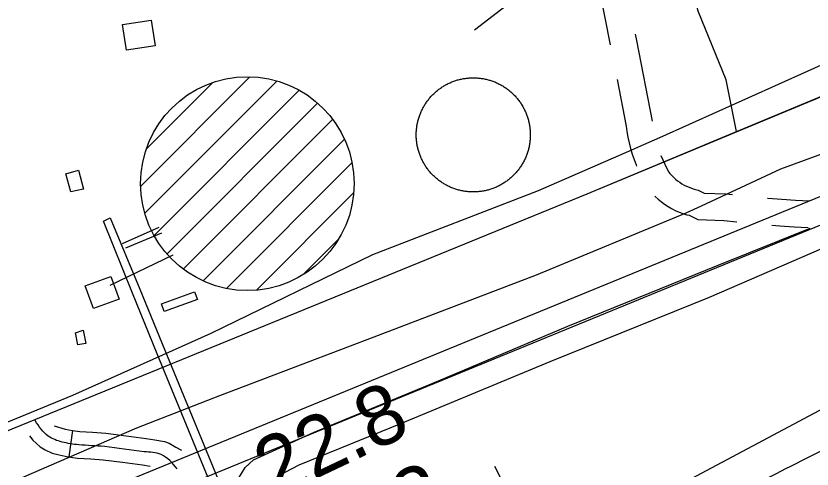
# Model space of a CAD drawing. Extents: x 3477039 to 3515015, y 546746 to 572297.
# Drawn here: x 3490723 to 3491621, y 565180 to 565690 of the extents above; entities that cross this region are included whole.
import ezdxf

# ---------------------------------------------------------------- set-up
doc = ezdxf.new("R2010")
doc.units = 0
for name, color, linetype in [('V-BLDG-OTLN', 7, 'Continuous'), ('V-DOMW-TANK', 7, 'Continuous'), ('V-FLOD-BASE', 7, 'Continuous'), ('V-LEVE-TOET', 7, 'Continuous'), ('V-RIVR-RANG', 7, 'Continuous'), ('V-ROAD-CNTR', 7, 'Continuous'), ('V-SITE-OTLN', 7, 'Continuous'), ('V-SITE-STRC', 7, 'Continuous'), ('V-SURV-LINE', 7, 'Continuous'), ('V-TOPO-MINR', 7, 'Continuous'), ('V-TOPO-SHOR', 7, 'Continuous'), ('V-UTIL-LINE', 7, 'Continuous')]:
    doc.layers.add(name, color=color, linetype=linetype)

msp = doc.modelspace()

# ---------------------------------------------------------------- linework, layer by layer
at = {"layer": 'V-BLDG-OTLN'}
for points in [[(3490875.75, 565685.23), (3490880.24, 565656.41), (3490847.93, 565651.37), (3490843.44, 565680.2)], [(3490799.44, 565495.05), (3490785.11, 565491.98), (3490779.51, 565512.16), (3490793.73, 565516.22)], [(3490839.59, 565370.95), (3490810.76, 565360.6), (3490801.59, 565386.16), (3490830.26, 565396.45)], [(3490928.18, 565370.91), (3490890.48, 565357.09), (3490887.33, 565365.82), (3490924.56, 565379.4)], [(3490799.26, 565336.03), (3490802.09, 565321.33), (3490793.15, 565319.61), (3490790.56, 565333.07)]]:
    msp.add_lwpolyline(points, close=True, dxfattribs=at)
at = {"layer": 'V-DOMW-TANK'}
for p, q in [((3490864.09, 565498.47), (3490986.95, 565621.33)), ((3490868.84, 565467.87), (3491017.61, 565616.64)), ((3490870.72, 565540.46), (3490944.98, 565614.72)), ((3490879.18, 565442.85), (3491042.7, 565606.37)), ((3490893.69, 565422.01), (3491063.33, 565591.65)), ((3490912.15, 565405.11), (3491080.35, 565573.32)), ((3490934.25, 565391.86), (3491093.67, 565551.28)), ((3490960.86, 565383.11), (3491102.18, 565524.44)), ((3490994.5, 565381.4), (3491104.15, 565491.05)), ((3491047.3, 565398.84), (3491086.35, 565437.9))]:
    msp.add_line(p, q, dxfattribs=at)
msp.add_circle((3490984.24, 565501.19), 120.38, dxfattribs=at)
at = {"layer": 'V-FLOD-BASE'}
msp.add_lwpolyline([(3490960.96, 565147.74), (3490981.75, 565181.62), (3490991.2, 565190.35), (3491059.5, 565221.52), (3491199.58, 565279.15), (3491345.56, 565340.84), (3491515.06, 565409.4), (3491618.64, 565450.87)], dxfattribs=at)
at = {"layer": 'V-LEVE-TOET'}
for points in [[(3491733.96, 565572.05), (3491585.1, 565517.43), (3491495.63, 565475.73), (3491478.53, 565467.76), (3491309.61, 565398.03), (3491134.84, 565331.27), (3490953.02, 565262.22), (3490859.45, 565225.95), (3490718.17, 565164.81), (3490576.91, 565106.02), (3490410.39, 565043.89), (3490383.11, 565035.49)], [(3491642.56, 565432.5), (3491504.81, 565373.1), (3491325.31, 565300.51), (3491156.97, 565230.77), (3491042.21, 565184.1), (3491018.64, 565171.95), (3491002.1, 565156.23), (3490973.57, 565107.75), (3490958.15, 565085.57), (3490949.9, 565081.52), (3490943.46, 565082.74), (3490907.83, 565105.31), (3490886.76, 565112.5), (3490869.76, 565113.8), (3490855.66, 565110.97), (3490841.54, 565106.39), (3490717.33, 565052.75), (3490582.56, 564998.6), (3490425.99, 564932.88), (3490344.85, 564899.28)]]:
    msp.add_lwpolyline(points, dxfattribs=at)
at = {"layer": 'V-ROAD-CNTR'}
msp.add_line((3490787.15, 565223.25), (3490783.09, 565193.52), dxfattribs=at)
for points in [[(3490529.31, 565147.85), (3491367.11, 565489.84), (3492727.74, 566054.53)], [(3491240.09, 565674.18), (3491275.99, 565701.54), (3491299.08, 565743.73), (3491305.03, 565770.31), (3491313.84, 565838.71), (3491328, 565872.96), (3491351.9, 565907.38), (3491386.23, 565937.6), (3491438.88, 565949.58), (3491522.88, 565981.17), (3491552.05, 565994.84), (3491588.38, 566018.94)], [(3491535.49, 565559.72), (3491523.85, 565617.9), (3491492.29, 565695.32), (3491472.88, 565768.14), (3491468.26, 565808.18), (3491479.57, 565829.14), (3491520.44, 565842.81), (3491575.69, 565851), (3491650, 565861.08), (3491647.65, 565868.29)], [(3491373.7, 565755.66), (3491375.41, 565747.18), (3491393.25, 565657.59)], [(3491421.44, 565669.62), (3491422.93, 565662.15), (3491440.72, 565571.5)], [(3491524.12, 565555), (3491737.96, 565643.75)], [(3491400.96, 565618.34), (3491411.27, 565565.8), (3491412.1, 565559.97), (3491413.26, 565553.53), (3491414.64, 565547.13), (3491416.25, 565540.79), (3491418.09, 565534.51), (3491420.15, 565528.3), (3491422.42, 565522.17), (3491422.92, 565520.96)], [(3490529.31, 565147.85), (3491367.11, 565489.84), (3491524.12, 565555)], [(3491450.48, 565532.82), (3491452.45, 565528.04), (3491454.71, 565523.06), (3491457.16, 565518.16), (3491459.27, 565514.27), (3491460.55, 565512.66), (3491462.54, 565510.43), (3491464.64, 565508.31), (3491466.85, 565506.31), (3491469.17, 565504.42), (3491471.59, 565502.67), (3491474.1, 565501.04), (3491476.68, 565499.56), (3491479.35, 565498.22), (3491482.08, 565497.03), (3491484.87, 565495.98), (3491487.71, 565495.09), (3491492.39, 565493.89), (3491499.29, 565490.6), (3491523.58, 565489.65), (3491531.04, 565488.78)], [(3491443.45, 565487.08), (3491443.91, 565486.61), (3491447.32, 565483.53), (3491450.89, 565480.63), (3491454.61, 565477.92), (3491458.47, 565475.42), (3491462.47, 565473.13), (3491466.58, 565471.06), (3491470.79, 565469.22), (3491475.09, 565467.61), (3491479.48, 565466.23), (3491482.12, 565465.55), (3491491.96, 565460.86), (3491521.26, 565459.72), (3491535.91, 565458.02)], [(3491570.61, 565484.81), (3491570.94, 565484.78), (3491586.52, 565483.6), (3491602.09, 565482.63), (3491617.75, 565481.87)], [(3491575.5, 565454.35), (3491584.45, 565453.67), (3491600.43, 565452.68), (3491616.3, 565451.91)], [(3490766.36, 565228.41), (3490778.99, 565224.89), (3490787.26, 565223.23), (3490795.57, 565222.1), (3490809.66, 565221.25), (3490824.69, 565220.15), (3490847.61, 565217.25), (3490870.11, 565214.18), (3490879.98, 565212.81), (3490890.8, 565210.76), (3490896.25, 565208.91), (3490903.76, 565204.32), (3490910.14, 565201.12)], [(3490738.6, 565217.08), (3490742.25, 565212.39), (3490750.8, 565204.87), (3490756.47, 565201.31), (3490764.29, 565197.85), (3490772.01, 565195.7), (3490782.28, 565193.64), (3490792.64, 565192.22), (3490807.67, 565191.32), (3490821.71, 565190.29), (3490843.69, 565187.5), (3490866.03, 565184.45), (3490874.84, 565183.24)], [(3491663.21, 565215.96), (3491615.72, 565192.39), (3491608.84, 565189.07), (3491602.43, 565185.9), (3491596.43, 565182.89), (3491590.82, 565180.05), (3491580.33, 565174.65), (3491562.01, 565165.12), (3491548.27, 565158), (3491543.11, 565155.35)]]:
    msp.add_lwpolyline(points, dxfattribs=at)
msp.add_spline([(3490905.22, 565179.92), (3490886.98, 565196.21), (3490868.07, 565199.31), (3490823.2, 565205.22), (3490794.1, 565207.16), (3490775.5, 565210.29), (3490759.8, 565216.93), (3490745.03, 565234.38)], degree=3, dxfattribs=at)
at = {"layer": 'V-SITE-OTLN'}
msp.add_lwpolyline([(3491649.27, 565642.8), (3491448.86, 565552.65), (3491430.69, 565544.9), (3491417.08, 565538.83), (3491312.12, 565493.17), (3491125.36, 565421.13), (3490943.17, 565332.61), (3490786.96, 565262.69), (3490573.06, 565175)], dxfattribs=at)
at = {"layer": 'V-SITE-STRC'}
for points in [[(3491177.44, 565574.89), (3491177.77, 565575.96), (3491178.13, 565577.02), (3491178.5, 565578.08), (3491178.9, 565579.13), (3491179.31, 565580.17), (3491179.74, 565581.21), (3491180.19, 565582.24), (3491180.65, 565583.26), (3491181.14, 565584.27), (3491181.64, 565585.27), (3491182.16, 565586.27), (3491182.69, 565587.26), (3491183.25, 565588.23), (3491183.82, 565589.2), (3491184.4, 565590.15), (3491185.01, 565591.1), (3491185.63, 565592.03), (3491186.26, 565592.96), (3491186.92, 565593.87), (3491187.58, 565594.78), (3491188.26, 565595.66), (3491188.96, 565596.54), (3491189.68, 565597.41), (3491190.41, 565598.26), (3491191.15, 565599.1), (3491191.91, 565599.93), (3491192.68, 565600.74), (3491193.47, 565601.54), (3491194.27, 565602.33), (3491195.08, 565603.1), (3491195.91, 565603.85), (3491196.75, 565604.6), (3491197.6, 565605.33), (3491198.47, 565606.04), (3491199.35, 565606.74), (3491200.24, 565607.42), (3491201.14, 565608.09), (3491202.06, 565608.74), (3491202.98, 565609.37), (3491203.92, 565609.99), (3491204.86, 565610.59), (3491205.82, 565611.18), (3491206.79, 565611.75), (3491207.76, 565612.3), (3491208.75, 565612.84), (3491209.75, 565613.35), (3491210.75, 565613.85), (3491211.76, 565614.33), (3491212.78, 565614.8), (3491213.81, 565615.25), (3491214.85, 565615.68), (3491215.89, 565616.09), (3491216.94, 565616.48), (3491218, 565616.85), (3491219.07, 565617.21), (3491220.14, 565617.55), (3491221.21, 565617.86), (3491222.3, 565618.16), (3491223.38, 565618.44), (3491224.47, 565618.7), (3491225.57, 565618.95), (3491226.67, 565619.17), (3491227.77, 565619.38), (3491228.88, 565619.56), (3491229.99, 565619.72), (3491231.1, 565619.87), (3491232.21, 565620), (3491233.33, 565620.1), (3491234.45, 565620.19), (3491235.57, 565620.26), (3491236.69, 565620.31), (3491237.81, 565620.34), (3491238.93, 565620.35), (3491240.05, 565620.34), (3491241.18, 565620.31), (3491242.3, 565620.26), (3491243.42, 565620.19), (3491244.54, 565620.1), (3491245.65, 565619.99), (3491246.77, 565619.87), (3491247.88, 565619.72), (3491248.99, 565619.55), (3491250.09, 565619.37), (3491251.2, 565619.16), (3491252.3, 565618.94), (3491253.39, 565618.7), (3491254.48, 565618.43), (3491255.57, 565618.15), (3491256.65, 565617.85), (3491257.72, 565617.53), (3491258.79, 565617.19), (3491259.86, 565616.84), (3491260.92, 565616.46), (3491261.97, 565616.07), (3491263.01, 565615.66), (3491264.05, 565615.23), (3491265.07, 565614.78), (3491266.1, 565614.32), (3491267.11, 565613.83), (3491268.11, 565613.33)], [(3491268.11, 565613.33), (3491269.11, 565612.81), (3491270.09, 565612.28), (3491271.07, 565611.73), (3491272.03, 565611.15), (3491272.99, 565610.57), (3491273.94, 565609.97), (3491274.87, 565609.35), (3491275.8, 565608.71), (3491276.71, 565608.06), (3491277.61, 565607.39), (3491278.5, 565606.71), (3491279.38, 565606.01), (3491280.24, 565605.3), (3491281.1, 565604.57), (3491281.94, 565603.82), (3491282.76, 565603.07), (3491283.57, 565602.29), (3491284.38, 565601.51), (3491285.16, 565600.71), (3491285.94, 565599.89), (3491286.69, 565599.07), (3491287.43, 565598.22), (3491288.16, 565597.37), (3491288.88, 565596.5), (3491289.58, 565595.63), (3491290.26, 565594.74), (3491290.92, 565593.83), (3491291.58, 565592.92), (3491292.21, 565592), (3491292.83, 565591.06), (3491293.43, 565590.11), (3491294.02, 565589.16), (3491294.59, 565588.19), (3491295.14, 565587.21), (3491295.67, 565586.23), (3491296.19, 565585.23), (3491296.69, 565584.23), (3491297.17, 565583.22), (3491297.64, 565582.2), (3491298.08, 565581.17), (3491298.51, 565580.13), (3491298.92, 565579.09), (3491299.31, 565578.04), (3491299.69, 565576.98), (3491300.05, 565575.92), (3491300.38, 565574.84), (3491300.7, 565573.77), (3491301, 565572.69), (3491301.28, 565571.6), (3491301.54, 565570.51), (3491301.78, 565569.42), (3491302.01, 565568.32), (3491302.21, 565567.21), (3491302.4, 565566.11), (3491302.56, 565565), (3491302.71, 565563.89), (3491302.83, 565562.77), (3491302.94, 565561.65), (3491303.03, 565560.54), (3491303.1, 565559.42), (3491303.14, 565558.3), (3491303.17, 565557.17), (3491303.18, 565556.05), (3491303.17, 565554.93), (3491303.14, 565553.81), (3491303.09, 565552.69), (3491303.02, 565551.57), (3491302.93, 565550.45), (3491302.83, 565549.33), (3491302.7, 565548.22), (3491302.55, 565547.11), (3491302.39, 565546), (3491302.2, 565544.89), (3491301.99, 565543.79), (3491301.77, 565542.69), (3491301.53, 565541.59), (3491301.27, 565540.51), (3491300.98, 565539.42), (3491300.68, 565538.34), (3491300.36, 565537.26), (3491300.03, 565536.19), (3491299.67, 565535.13), (3491299.29, 565534.07), (3491298.9, 565533.02), (3491298.49, 565531.98), (3491298.06, 565530.94), (3491297.61, 565529.91), (3491297.15, 565528.89), (3491296.66, 565527.88), (3491296.16, 565526.88), (3491295.64, 565525.88), (3491295.11, 565524.9), (3491294.55, 565523.92), (3491293.98, 565522.95), (3491293.4, 565522), (3491292.79, 565521.05), (3491292.17, 565520.11), (3491291.54, 565519.19), (3491290.89, 565518.28), (3491290.22, 565517.38)], [(3491231.03, 565492.28), (3491229.92, 565492.43), (3491228.81, 565492.6), (3491227.71, 565492.78), (3491226.6, 565492.99), (3491225.5, 565493.21), (3491224.41, 565493.46), (3491223.32, 565493.72), (3491222.23, 565494), (3491221.15, 565494.3), (3491220.07, 565494.62), (3491219, 565494.95), (3491217.94, 565495.31), (3491216.88, 565495.69), (3491215.83, 565496.08), (3491214.79, 565496.49), (3491213.75, 565496.92), (3491212.72, 565497.37), (3491211.7, 565497.83), (3491210.69, 565498.32), (3491209.69, 565498.82), (3491208.69, 565499.34), (3491207.71, 565499.87), (3491206.73, 565500.43), (3491205.76, 565500.99), (3491204.81, 565501.58), (3491203.86, 565502.18), (3491202.93, 565502.8), (3491202, 565503.44), (3491201.09, 565504.09), (3491200.19, 565504.76), (3491199.3, 565505.44), (3491198.42, 565506.14), (3491197.55, 565506.85), (3491196.7, 565507.58), (3491195.86, 565508.33), (3491195.04, 565509.09), (3491194.22, 565509.86), (3491193.42, 565510.65), (3491192.64, 565511.45), (3491191.87, 565512.26), (3491191.11, 565513.09), (3491190.36, 565513.93), (3491189.63, 565514.78), (3491188.92, 565515.65), (3491188.22, 565516.52), (3491187.54, 565517.41), (3491186.88, 565518.32), (3491186.22, 565519.23), (3491185.59, 565520.15), (3491184.97, 565521.09), (3491184.37, 565522.04), (3491183.78, 565522.99), (3491183.21, 565523.96), (3491182.66, 565524.93), (3491182.12, 565525.92), (3491181.61, 565526.92), (3491181.11, 565527.92), (3491180.62, 565528.93), (3491180.16, 565529.95), (3491179.71, 565530.98), (3491179.29, 565532.02), (3491178.87, 565533.06), (3491178.48, 565534.11), (3491178.11, 565535.17), (3491177.75, 565536.24), (3491177.42, 565537.31), (3491177.1, 565538.38), (3491176.8, 565539.46), (3491176.52, 565540.55), (3491176.26, 565541.64), (3491176.02, 565542.73), (3491175.79, 565543.83), (3491175.59, 565544.94), (3491175.4, 565546.04), (3491175.24, 565547.15), (3491175.09, 565548.26), (3491174.97, 565549.38), (3491174.86, 565550.5), (3491174.77, 565551.61), (3491174.7, 565552.73), (3491174.66, 565553.85), (3491174.63, 565554.98), (3491174.62, 565556.1), (3491174.63, 565557.22), (3491174.66, 565558.34), (3491174.71, 565559.46), (3491174.78, 565560.58), (3491174.86, 565561.7), (3491174.97, 565562.82), (3491175.1, 565563.93), (3491175.25, 565565.05), (3491175.41, 565566.15), (3491175.6, 565567.26), (3491175.81, 565568.36), (3491176.03, 565569.46), (3491176.27, 565570.56), (3491176.54, 565571.65), (3491176.82, 565572.73), (3491177.12, 565573.81), (3491177.44, 565574.89)], [(3491290.22, 565517.38), (3491289.53, 565516.49), (3491288.83, 565515.61), (3491288.12, 565514.74), (3491287.39, 565513.89), (3491286.65, 565513.05), (3491285.89, 565512.22), (3491285.12, 565511.41), (3491284.33, 565510.61), (3491283.53, 565509.83), (3491282.72, 565509.05), (3491281.89, 565508.29), (3491281.05, 565507.55), (3491280.19, 565506.83), (3491279.33, 565506.11), (3491278.45, 565505.41), (3491277.56, 565504.73), (3491276.66, 565504.07), (3491275.74, 565503.41), (3491274.82, 565502.78), (3491273.88, 565502.16), (3491272.94, 565501.56), (3491271.98, 565500.97), (3491271.01, 565500.4), (3491270.04, 565499.85), (3491269.05, 565499.32), (3491268.05, 565498.8), (3491267.05, 565498.3), (3491266.04, 565497.81), (3491265.02, 565497.35), (3491263.98, 565496.9), (3491262.95, 565496.47), (3491261.9, 565496.06), (3491260.85, 565495.67), (3491259.8, 565495.3), (3491258.73, 565494.94), (3491257.66, 565494.6), (3491256.58, 565494.29), (3491255.5, 565493.99), (3491254.42, 565493.71), (3491253.33, 565493.44), (3491252.23, 565493.2), (3491251.13, 565492.98), (3491250.03, 565492.78), (3491248.92, 565492.59), (3491247.81, 565492.43), (3491246.7, 565492.28), (3491245.59, 565492.15), (3491244.47, 565492.05), (3491243.35, 565491.96), (3491242.23, 565491.89), (3491241.11, 565491.84), (3491239.99, 565491.81), (3491238.87, 565491.8), (3491237.74, 565491.81), (3491236.62, 565491.84), (3491235.5, 565491.89), (3491234.38, 565491.96), (3491233.26, 565492.05), (3491232.15, 565492.16), (3491231.03, 565492.28)], [(3490829.71, 565462.55), (3490863.14, 565382.5), (3490891.38, 565313.64), (3491157.63, 564667.97), (3491148.22, 564664.52), (3490882.55, 565309.6), (3490854.9, 565377.87), (3490822.06, 565459.09), (3490829.71, 565462.55)]]:
    msp.add_lwpolyline(points, dxfattribs=at)
at = {"layer": 'V-SURV-LINE'}
for points in [[(3490213.26, 564906.46), (3492072.24, 565667.9)], [(3492083.62, 565640.14), (3490224.63, 564878.7)]]:
    msp.add_lwpolyline(points, dxfattribs=at)
at = {"layer": 'V-TOPO-MINR'}
msp.add_lwpolyline([(3492227.36, 565563.96), (3491271.58, 565055.61)], dxfattribs=at)
at = {"layer": 'V-TOPO-SHOR'}
msp.add_lwpolyline([(3491262.74, 565183.26), (3491313.7, 565084.77), (3491339.14, 565029.36), (3491345.8, 565015.34)], dxfattribs=at)
at = {"layer": 'V-UTIL-LINE'}
for p, q in [((3490884.48, 565451.85), (3490843.22, 565433.36)), ((3490887.37, 565445.37), (3490846.71, 565428.64)), ((3490900.11, 565420.6), (3490829.36, 565386.47))]:
    msp.add_line(p, q, dxfattribs=at)

# ---------------------------------------------------------------- texts
at = {"layer": 'V-RIVR-RANG'}
for s, p in [('22.8', (3491013.35, 565145.97)), ('21.3', (3491056.44, 565055.73))]:
    msp.add_text(s, height=67, rotation=25.37833, dxfattribs=at).set_placement(p)

doc.saveas('drawing.dxf')
